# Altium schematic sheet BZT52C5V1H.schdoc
size 127 x 101 mm
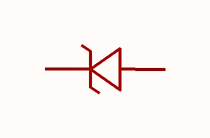
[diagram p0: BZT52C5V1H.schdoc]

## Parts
D?  bzt52c5v1h  [SOD-123_L2.7-W1.6-LS3.7-RD-1]  (value not drawn)

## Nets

Not connected (* = marked no-connect by the designer): D? 1(K) 2(A)

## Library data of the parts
D? = bzt52c5v1h: 二极管配置:1个独立式;稳压值(标称值):5.1V;稳压值(范围值):5.1V~5.5V;耗散功率(Pd):500mW;; Manufacturer: CJ(江苏长电/长晶); AddInBom: yes; ModelId: 528459655f7d4601a76356f3191c812b; ModelTransform: 151.575,66.929,0,0,0,0,0,0,0; Diode Configuration: 1个独立式; Zener Voltage(Nom): 5.1V; Reverse Leakage Current (Ir): 50uA; Pd - Power Dissipation: 500mW; Impedance(Zzt): 50Ω; Impedance(Zzk): 450Ω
